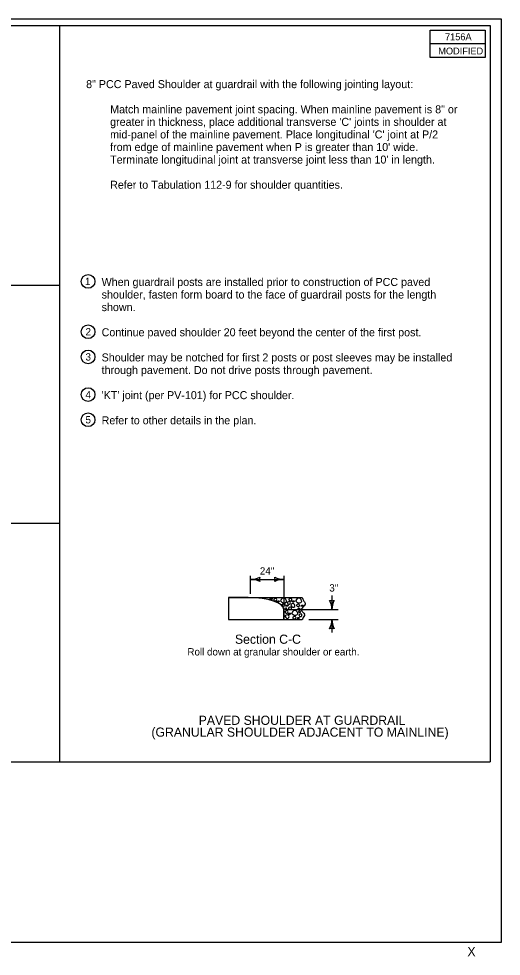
# Model space of a CAD drawing. Extents: x 9538 to 81668, y 7600 to 11751.
# Drawn here: x 12213 to 13268, y 7894 to 9944 of the extents above; entities that cross this region are included whole.
import ezdxf

# ---------------------------------------------------------------- set-up
doc = ezdxf.new("R2010")
doc.units = 0
for name, color, linetype in [('Default', 7, 'Continuous'), ('DsnShtMinorGrid12', 7, 'Continuous'), ('DsnShtMinorGrid13', 7, 'Continuous'), ('dsnStdBlockNotModified', 7, 'Continuous'), ('dsnStdCells', 7, 'Continuous'), ('dsnStdDimension', 7, 'Continuous'), ('dsnStdNameDate', 7, 'Continuous'), ('dsnStdNote', 7, 'Continuous'), ('dsnStdShading', 7, 'Continuous'), ('dsnStdTable', 7, 'Continuous'), ('Level 9', 7, 'Continuous')]:
    doc.layers.add(name, color=color, linetype=linetype)

msp = doc.modelspace()

# ---------------------------------------------------------------- linework, layer by layer
at = {"layer": 'Default'}
msp.add_lwpolyline([(10132.5, 9944), (13267.5, 9944), (13267.5, 7924), (10132.5, 7924)], close=True, dxfattribs=at)
at = {"layer": 'DsnShtMinorGrid12'}
for points in [[(12764.3, 8674.1), (12765.1, 8673.9), (12765.7, 8673.9), (12768.1, 8676.3), (12764, 8677.1), (12760.6, 8675), (12763.4, 8674.3), (12764.3, 8674.1)], [(12770.7, 8674.6), (12770.8, 8675.1), (12771.1, 8675), (12775.7, 8677.6), (12778.1, 8674.4), (12775.9, 8670.4), (12770.8, 8671.5), (12770.7, 8674), (12770.7, 8674.6)], [(12785.6, 8670.8), (12785.3, 8671.3), (12785.8, 8670.9), (12787.7, 8677.4), (12796, 8677.6), (12798.7, 8670.4), (12799, 8669.6), (12794.2, 8665.8), (12787.5, 8668), (12785.8, 8670.3), (12785.6, 8670.8)], [(12803.6, 8674.6), (12803.7, 8675.1), (12804, 8675), (12808.6, 8677.6), (12811, 8674.4), (12808.9, 8670.4), (12803.8, 8671.5), (12803.6, 8674), (12803.6, 8674.6)], [(12818.5, 8670.8), (12818.2, 8671.3), (12818.8, 8670.9), (12820.6, 8677.4), (12829, 8677.6), (12831.6, 8670.4), (12831.9, 8669.6), (12827.1, 8665.8), (12820.4, 8668), (12818.8, 8670.3), (12818.5, 8670.8)], [(12779.9, 8668.6), (12780.8, 8668.4), (12781.3, 8668.4), (12783.7, 8670.8), (12779.7, 8671.6), (12776.2, 8669.5), (12779.1, 8668.7), (12779.9, 8668.6)], [(12789.1, 8663.3), (12789.1, 8663.9), (12789.5, 8663.7), (12794, 8666.4), (12796.5, 8663.2), (12794.3, 8659.2), (12789.2, 8660.2), (12789, 8662.7), (12789.1, 8663.3)], [(12794.5, 8653.6), (12794.1, 8654.1), (12794.4, 8654.5), (12798.7, 8655.8), (12800, 8652.3), (12796.8, 8651.5), (12794.9, 8653.2), (12794.5, 8653.6)], [(12799.2, 8659.3), (12800, 8659.1), (12800.6, 8659.1), (12803, 8661.6), (12799, 8662.4), (12795.5, 8660.2), (12798.3, 8659.5), (12799.2, 8659.3)], [(12800.1, 8667.4), (12800.1, 8668), (12800.5, 8667.8), (12805.1, 8670.5), (12807.5, 8667.3), (12805.3, 8663.2), (12800.2, 8664.3), (12800.1, 8666.8), (12800.1, 8667.4)], [(12803, 8655.6), (12803, 8656.2), (12803.4, 8656), (12807.9, 8658.7), (12810.3, 8655.4), (12808.2, 8651.4), (12803.1, 8652.5), (12802.9, 8655), (12803, 8655.6)], [(12808.2, 8661.4), (12807.6, 8662.5), (12807.8, 8662.9), (12812.3, 8665.8), (12816.4, 8664), (12817.4, 8658.6), (12811.3, 8655.9), (12808.8, 8660.2), (12808.2, 8661.4)], [(12812.8, 8668.6), (12813.7, 8668.4), (12814.2, 8668.4), (12816.6, 8670.8), (12812.6, 8671.6), (12809.1, 8669.5), (12812, 8668.7), (12812.8, 8668.6)], [(12820.4, 8662), (12820.4, 8662.6), (12820.8, 8662.4), (12825.3, 8665.1), (12827.7, 8661.9), (12825.6, 8657.9), (12820.5, 8658.9), (12820.3, 8661.4), (12820.4, 8662)], [(12823.1, 8653.2), (12822.7, 8653.7), (12823.1, 8654.1), (12827.3, 8655.4), (12828.7, 8651.9), (12825.5, 8651.1), (12823.5, 8652.7), (12823.1, 8653.2)], [(12832.1, 8659.3), (12833, 8659.1), (12833.5, 8659.1), (12835.9, 8661.6), (12831.9, 8662.4), (12828.4, 8660.2), (12831.3, 8659.5), (12832.1, 8659.3)], [(12795.6, 8636.9), (12795.1, 8638), (12795.2, 8638.4), (12799.8, 8641.3), (12803.8, 8639.4), (12804.9, 8634.1), (12798.7, 8631.4), (12796.2, 8635.7), (12795.6, 8636.9)], [(12795.2, 8647.4), (12795.3, 8648), (12795.6, 8647.8), (12800.2, 8650.5), (12802.6, 8647.3), (12800.4, 8643.3), (12795.4, 8644.3), (12795.2, 8646.8), (12795.2, 8647.4)], [(12804.4, 8641.4), (12805.3, 8641.3), (12805.8, 8641.3), (12808.2, 8643.7), (12804.2, 8644.5), (12800.7, 8642.3), (12803.6, 8641.6), (12804.4, 8641.4)], [(12810.1, 8643.7), (12809.8, 8644.2), (12810.4, 8643.8), (12812.2, 8650.2), (12820.5, 8650.5), (12823.2, 8643.3), (12823.5, 8642.5), (12818.7, 8638.7), (12812, 8640.9), (12810.4, 8643.2), (12810.1, 8643.7)], [(12812, 8634.9), (12812, 8635.5), (12812.4, 8635.3), (12816.9, 8638), (12819.3, 8634.7), (12817.2, 8630.7), (12812.1, 8631.8), (12811.9, 8634.3), (12812, 8634.9)], [(12823.7, 8632.2), (12824.6, 8632), (12825.1, 8632), (12827.5, 8634.4), (12823.5, 8635.2), (12820, 8633.1), (12822.9, 8632.4), (12823.7, 8632.2)], [(12824.4, 8647.1), (12824, 8647.6), (12824.4, 8648), (12828.7, 8649.3), (12830, 8645.8), (12826.8, 8645), (12824.8, 8646.6), (12824.4, 8647.1)], [(12825.5, 8640.3), (12825.6, 8640.9), (12825.9, 8640.7), (12830.5, 8643.4), (12832.9, 8640.2), (12830.8, 8636.2), (12825.7, 8637.2), (12825.5, 8639.7), (12825.5, 8640.3)]]:
    msp.add_open_spline(points, degree=3, dxfattribs=at)
at = {"layer": 'DsnShtMinorGrid13'}
for centre in [(12364.9, 9369.6), (12364.9, 9259.6), (12364.9, 9204.6), (12364.9, 9122.1), (12364.9, 9067.1)]:
    msp.add_circle(centre, 15, dxfattribs=at)
at = {"layer": 'dsnStdCells'}
for p, q in [((12714.7, 8678.3), (12671.6, 8678.3)), ((12671.6, 8678.3), (12671.6, 8630.3)), ((12792.5, 8630.3), (12792.5, 8652.1)), ((12671.6, 8630.3), (12792.5, 8630.3))]:
    msp.add_line(p, q, dxfattribs=at)
msp.add_lwpolyline([(12714.7, 8678.3), (12714.7, 8678.3)], dxfattribs=at)
msp.add_ellipse((12714.7, 8652.1), major_axis=(77.9, 0), ratio=0.335273, start_param=0, end_param=1.570796, dxfattribs=at)
at = {"layer": 'dsnStdDimension'}
for p, q in [((12720, 8686.8), (12720, 8726.2)), ((12720, 8718.2), (12792.5, 8718.2)), ((12792.5, 8726.2), (12792.5, 8662.7)), ((12897.6, 8683.1), (12897.6, 8652.1)), ((12799.3, 8652.1), (12911.4, 8652.1)), ((12847.3, 8630.3), (12911.4, 8630.3)), ((12897.6, 8630.3), (12897.6, 8601.7))]:
    msp.add_line(p, q, dxfattribs=at)
for centre, radius, start, end in [((12720, 8760.7), 42.5, 270, 298.0725), ((12720, 8675.7), 42.5, 61.9275, 90), ((12755.6, 8718.2), 16.4, 162.2666, 197.7334), ((12756.9, 8718.2), 16.4, 342.2666, 17.7334), ((12792.5, 8760.7), 42.5, 241.9275, 270), ((12792.5, 8675.7), 42.5, 90, 118.0725), ((12897.6, 8687.8), 16.4, 252.2666, 287.7334), ((12855.1, 8652.1), 42.5, 0, 28.0725), ((12940.1, 8652.1), 42.5, 151.9275, 180), ((12855.1, 8630.3), 42.5, 331.9275, 360), ((12897.6, 8594.7), 16.4, 72.2666, 107.7334), ((12940.1, 8630.3), 42.5, 180, 208.0725)]:
    msp.add_arc(centre, radius, start, end, dxfattribs=at)
at = {"layer": 'dsnStdNameDate'}
for p, q in [((12303.1, 8319), (12303.1, 9929)), ((12303.1, 9361), (10147.5, 9361)), ((12303.1, 8840), (10147.5, 8840))]:
    msp.add_line(p, q, dxfattribs=at)
at = {"layer": 'dsnStdShading'}
for p, q in [((10147.5, 9929), (13243.2, 9929)), ((13243.2, 9929), (13243.2, 8319)), ((10147.5, 8319), (13243.2, 8319))]:
    msp.add_line(p, q, dxfattribs=at)
at = {"layer": 'dsnStdTable'}
for p, q in [((13243.2, 9929), (13243.2, 9929)), ((12671.6, 8678.3), (12671.6, 8630.3)), ((12671.6, 8678.3), (12714.7, 8678.3)), ((12714.7, 8678.3), (12832.4, 8678.3)), ((12792.5, 8652.1), (12792.5, 8630.3)), ((12671.6, 8630.3), (12792.5, 8630.3)), ((12792.5, 8630.3), (12832.4, 8630.3))]:
    msp.add_line(p, q, dxfattribs=at)
msp.add_lwpolyline([(13232.3, 9919), (13232.3, 9859), (13112.6, 9859), (13112.6, 9919), (13232.3, 9919), (13232.3, 9889), (13112.6, 9889)], dxfattribs=at)
msp.add_ellipse((12714.7, 8652.1), major_axis=(77.9, 0), ratio=0.335273, start_param=0, end_param=1.570796, dxfattribs=at)
msp.add_spline([(12832.4, 8678.3), (12833.8, 8675.1), (12835.6, 8671.9), (12837.5, 8668.9), (12838.9, 8665.8), (12839.1, 8664.1), (12838.4, 8662.3), (12835.5, 8658.8), (12832.4, 8655.3), (12831.3, 8653.6), (12830.9, 8652.7), (12830.8, 8651.8), (12830.8, 8651.4), (12831.2, 8650.2), (12832.2, 8648.7), (12835.1, 8645.5), (12837.6, 8642.3), (12838.1, 8640.7), (12838, 8639.9), (12837.8, 8639.5), (12837.6, 8639.1), (12832.3, 8630.4)], degree=3, dxfattribs=at)

# ---------------------------------------------------------------- texts
at = {"layer": 'DsnShtMinorGrid13'}
for s, height, p in [('8" PCC Paved Shoulder at guardrail with the following jointing layout:', 17.5, (12360.5, 9792.3)), ('Match mainline pavement joint spacing. When mainline pavement is 8" or ', 17.5, (12413, 9737.3)), ("greater in thickness, place additional transverse 'C' joints in shoulder at ", 17.5, (12413, 9709.8)), ("mid-panel of the mainline pavement. Place longitudinal 'C' joint at P/2 ", 17.5, (12413, 9682.3)), ("from edge of mainline pavement when P is greater than 10' wide. ", 17.5, (12413, 9654.8)), ("Terminate longitudinal joint at transverse joint less than 10' in length.", 17.5, (12413, 9627.3)), ('Refer to Tabulation 112-9 for shoulder quantities.', 17.5, (12413, 9572.3)), ('1', 16, (12358.1, 9361.6)), ('When guardrail posts are installed prior to construction of PCC paved ', 17.5, (12394.4, 9359.7)), ('shoulder, fasten form board to the face of guardrail posts for the length ', 17.5, (12394.4, 9332.2)), ('shown.', 17.5, (12394.4, 9304.7)), ('2', 16, (12359.3, 9251.6)), ('Continue paved shoulder 20 feet beyond the center of the first post.', 17.5, (12394.4, 9249.7)), ('3', 16, (12359.2, 9196.6)), ('Shoulder may be notched for first 2 posts or post sleeves may be installed ', 17.5, (12394.4, 9194.7)), ('through pavement. Do not drive posts through pavement.', 17.5, (12394.4, 9167.2)), ('4', 16, (12359.3, 9114.1)), ("'KT' joint (per PV-101) for PCC shoulder.", 17.5, (12394.4, 9112.2)), ('5', 16, (12359.2, 9059.1)), ('Refer to other details in the plan.', 17.5, (12394.4, 9057.2))]:
    msp.add_text(s, height=height, dxfattribs=at).set_placement(p)
at = {"layer": 'dsnStdBlockNotModified'}
msp.add_text('X', height=20, dxfattribs=at).set_placement((13193.6, 7894))
at = {"layer": 'dsnStdDimension'}
for s, p in [("24''", (12740.1, 8728.5)), ("3'' ", (12891.9, 8691.5))]:
    msp.add_text(s, height=16, dxfattribs=at).set_placement(p)
at = {"layer": 'dsnStdNote'}
for s, height, p in [('Section C-C', 20, (12685.7, 8577.3)), ('Roll down at granular shoulder or earth.', 16, (12581.9, 8551.7)), ('PAVED SHOULDER AT GUARDRAIL', 20, (12606.5, 8400)), ('(GRANULAR SHOULDER ADJACENT TO MAINLINE)', 20, (12503.2, 8374.1))]:
    msp.add_text(s, height=height, dxfattribs=at).set_placement(p)
at = {"layer": 'Level 9'}
for s, p in [('7156A', (13144.7, 9897)), ('MODIFIED', (13130, 9866))]:
    msp.add_text(s, height=15, dxfattribs=at).set_placement(p)

doc.saveas('drawing.dxf')
